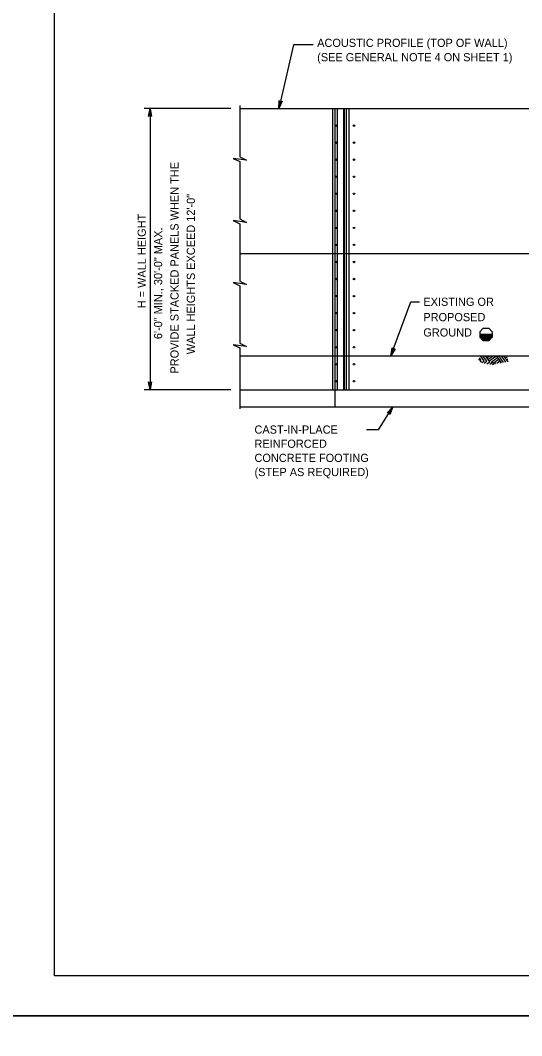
# Model space of a CAD drawing. Extents: x 3385 to 6532, y -616 to 1166.
# Drawn here: x 5470.5 to 5658.6, y 564.2 to 945.5 of the extents above; entities that cross this region are included whole.
import ezdxf

# ---------------------------------------------------------------- set-up
doc = ezdxf.new("R2010")
doc.units = 0
for name, color, linetype in [('1', 7, 'Continuous'), ('2', 7, 'Continuous'), ('PLT-BNDY', 7, 'Continuous')]:
    doc.layers.add(name, color=color, linetype=linetype)

msp = doc.modelspace()

# ---------------------------------------------------------------- linework, layer by layer
at = {"layer": '1'}
for p, q in [((5573, 936.35), (5567.47, 912.36)), ((5580.4, 936.35), (5573, 936.35)), ((5549.4, 912.36), (5516.97, 912.36)), ((5519.16, 912.36), (5519.16, 806.75)), ((5552.78, 913.58), (5552.78, 894.22)), ((5552.78, 912.36), (5684.01, 912.36)), ((5587.59, 912.36), (5587.59, 806.75)), ((5588.65, 806.75), (5588.65, 912.36)), ((5589.53, 806.75), (5589.53, 912.36)), ((5591.91, 806.75), (5591.91, 912.36)), ((5592.15, 806.75), (5592.15, 912.36)), ((5592.77, 912.36), (5592.77, 806.75)), ((5593.85, 806.75), (5593.85, 912.36)), ((5552.78, 892.46), (5552.78, 870.9)), ((5552.78, 869.14), (5552.78, 847.59)), ((5552.78, 857.95), (5771.06, 857.95)), ((5552.78, 845.83), (5552.78, 824.27)), ((5609.52, 819.55), (5617.03, 839.74)), ((5617.03, 839.74), (5620.3, 839.74)), ((5642.89, 827.65), (5647.51, 827.65)), ((5644.16, 829.84), (5642.91, 828.58)), ((5642.91, 828.58), (5642.91, 826.47)), ((5642.92, 827.55), (5647.51, 827.55)), ((5644.16, 829.84), (5646.27, 829.84)), ((5646, 827.65), (5647.51, 827.65)), ((5646.27, 829.84), (5647.52, 828.58)), ((5647.52, 828.58), (5647.52, 826.47)), ((5642.89, 826.55), (5647.51, 826.55)), ((5642.9, 826.95), (5647.51, 826.95)), ((5642.9, 826.85), (5647.51, 826.85)), ((5642.9, 826.75), (5647.51, 826.75)), ((5642.9, 826.65), (5647.51, 826.65)), ((5642.91, 827.45), (5647.51, 827.45)), ((5642.91, 827.35), (5647.51, 827.35)), ((5642.91, 827.25), (5647.51, 827.25)), ((5642.91, 827.15), (5647.51, 827.15)), ((5642.91, 827.05), (5647.51, 827.05)), ((5644.16, 825.21), (5642.91, 826.47)), ((5642.91, 826.45), (5647.47, 826.45)), ((5643.02, 826.35), (5647.37, 826.35)), ((5643.12, 826.25), (5647.28, 826.25)), ((5643.22, 826.15), (5647.18, 826.15)), ((5643.32, 826.05), (5647.08, 826.05)), ((5643.42, 825.95), (5646.99, 825.95)), ((5643.53, 825.85), (5646.89, 825.85)), ((5643.63, 825.75), (5646.8, 825.75)), ((5643.73, 825.65), (5646.7, 825.65)), ((5643.83, 825.55), (5646.6, 825.55)), ((5643.93, 825.45), (5646.51, 825.45)), ((5644.03, 825.35), (5646.41, 825.35)), ((5644.14, 825.25), (5646.32, 825.25)), ((5644.16, 825.21), (5646.27, 825.21)), ((5646.27, 825.21), (5647.52, 826.47)), ((5552.78, 822.51), (5552.78, 799.62)), ((5552.78, 819.55), (5769.29, 819.55)), ((5642.53, 818.1), (5643.01, 818.43)), ((5643.44, 817.81), (5642.74, 818.81)), ((5643.46, 817.13), (5642.91, 817.91)), ((5644.49, 817.63), (5643.15, 819.54)), ((5643.65, 817.04), (5644.49, 817.63)), ((5645.54, 817.45), (5644.07, 819.53)), ((5644.55, 816.75), (5645.54, 817.45)), ((5646.59, 817.26), (5645, 819.53)), ((5645.07, 819.42), (5645.23, 819.53)), ((5645.51, 818.81), (5646.54, 819.53)), ((5645.58, 816.56), (5646.59, 817.26)), ((5645.94, 818.19), (5647.84, 819.53)), ((5646.38, 817.57), (5647.92, 818.66)), ((5646.62, 816.36), (5647.64, 817.08)), ((5647.12, 817.17), (5647.73, 817.6)), ((5648.22, 816.25), (5647.64, 817.08)), ((5647.65, 816.16), (5648.08, 816.46)), ((5647.73, 817.6), (5649.59, 818.91)), ((5647.92, 818.66), (5649.15, 819.52)), ((5648.17, 816.99), (5650.02, 818.29)), ((5648.95, 816.52), (5648.69, 816.9)), ((5651, 816.9), (5649.15, 819.52)), ((5649.22, 816.8), (5650.45, 817.67)), ((5651.84, 817.02), (5650.08, 819.52)), ((5650.58, 816.84), (5650.89, 817.05)), ((5652.67, 817.13), (5651, 819.52)), ((5653.51, 817.25), (5651.92, 819.52)), ((5652.09, 819.28), (5652.42, 819.51)), ((5652.52, 818.66), (5653.17, 819.12)), ((5652.96, 818.05), (5653.35, 818.32)), ((5653.39, 817.43), (5653.53, 817.53)), ((5549.4, 806.75), (5516.97, 806.75)), ((5552.78, 806.75), (5771.3, 806.75)), ((5588.55, 800.35), (5588.55, 806.75)), ((5552.78, 800.35), (5752.12, 800.35)), ((5604.84, 791.67), (5610.23, 800.35)), ((5604.84, 791.67), (5600.37, 791.67))]:
    msp.add_line(p, q, dxfattribs=at)
for points in [[(5567.47, 912.36), (5567.6, 915.39), (5567.7, 915.13), (5567.87, 914.97), (5568.06, 914.89), (5568.26, 914.88), (5568.48, 914.95), (5568.69, 915.14), (5567.47, 912.36), (5568.48, 914.95), (5568.26, 914.88), (5567.47, 912.36), (5568.06, 914.89), (5567.87, 914.97), (5567.47, 912.36), (5567.7, 915.13)], [(5519.16, 912.36), (5519.72, 909.37), (5519.56, 909.6), (5519.36, 909.72), (5519.16, 909.76), (5518.96, 909.72), (5518.76, 909.6), (5518.6, 909.37), (5519.16, 912.36), (5518.76, 909.6), (5518.96, 909.72), (5519.16, 912.36), (5519.16, 909.76), (5519.36, 909.72), (5519.16, 912.36), (5519.56, 909.6)], [(5552.78, 894.22), (5555.37, 892.95), (5550.29, 893.64), (5552.78, 892.46)], [(5552.78, 870.9), (5555.37, 869.63), (5550.29, 870.32), (5552.78, 869.14)], [(5552.78, 847.59), (5555.37, 846.32), (5550.29, 847.01), (5552.78, 845.83)], [(5552.78, 824.27), (5555.37, 823), (5550.29, 823.69), (5552.78, 822.51)], [(5609.52, 819.55), (5610.04, 822.54), (5610.07, 822.41), (5610.11, 822.27), (5610.18, 822.18), (5610.25, 822.09), (5610.34, 822.04), (5610.43, 821.99), (5610.53, 821.97), (5610.63, 821.95), (5610.74, 821.97), (5610.86, 821.99), (5610.97, 822.07), (5611.08, 822.15), (5609.52, 819.55), (5610.97, 822.07), (5610.86, 821.99), (5609.52, 819.55), (5610.74, 821.97), (5610.63, 821.95), (5609.52, 819.55), (5610.53, 821.97), (5610.43, 821.99), (5609.52, 819.55), (5610.34, 822.04), (5610.25, 822.09), (5609.52, 819.55), (5610.18, 822.18), (5610.11, 822.27), (5609.52, 819.55), (5610.07, 822.41)], [(5519.16, 806.75), (5518.6, 809.74), (5518.68, 809.62), (5518.76, 809.51), (5518.86, 809.45), (5518.96, 809.39), (5519.06, 809.37), (5519.16, 809.35), (5519.26, 809.37), (5519.36, 809.39), (5519.46, 809.45), (5519.56, 809.51), (5519.64, 809.62), (5519.72, 809.74), (5519.16, 806.75), (5519.64, 809.62), (5519.56, 809.51), (5519.16, 806.75), (5519.46, 809.45), (5519.36, 809.39), (5519.16, 806.75), (5519.26, 809.37), (5519.16, 809.35), (5519.16, 806.75), (5519.06, 809.37), (5518.96, 809.39), (5519.16, 806.75), (5518.86, 809.45), (5518.76, 809.51), (5519.16, 806.75), (5518.68, 809.62)], [(5610.23, 800.35), (5609.13, 797.52), (5609.12, 797.8), (5609.01, 798.01), (5608.86, 798.15), (5608.67, 798.22), (5608.44, 798.23), (5608.18, 798.11), (5610.23, 800.35), (5608.44, 798.23), (5608.67, 798.22), (5610.23, 800.35), (5608.86, 798.15), (5609.01, 798.01), (5610.23, 800.35), (5609.12, 797.8)]]:
    msp.add_lwpolyline(points, dxfattribs=at)
for centre in [(5589.09, 905.96), (5595.66, 905.96), (5589.09, 899.56), (5595.66, 899.56), (5589.09, 893.16), (5595.66, 893.16), (5589.09, 886.76), (5595.66, 886.76), (5589.09, 880.36), (5595.66, 880.36), (5589.09, 873.96), (5595.66, 873.96), (5589.09, 867.56), (5595.66, 867.56), (5589.09, 861.15), (5595.66, 861.15), (5589.09, 854.75), (5595.66, 854.75), (5589.09, 848.35), (5595.66, 848.35), (5589.09, 841.95), (5595.66, 841.95), (5589.09, 835.55), (5595.66, 835.55), (5589.09, 829.15), (5595.66, 829.15), (5589.09, 822.75), (5595.66, 822.75), (5589.09, 816.35), (5595.66, 816.35), (5589.09, 809.95), (5595.66, 809.95)]:
    msp.add_circle(centre, 0.267, dxfattribs=at)
at = {"layer": '2'}
for p, q in [((5483.34, 586.69), (5483.34, 1150.69)), ((6269.34, 586.69), (5483.34, 586.69))]:
    msp.add_line(p, q, dxfattribs=at)
at = {"layer": 'PLT-BNDY'}
for points in [[(5443.34, 1165.69), (6284.34, 1165.69), (6284.34, 571.69), (5443.34, 571.69)], [(5443.34, 571.69), (6284.34, 571.69), (6284.34, -22.31), (5443.34, -22.31)]]:
    msp.add_lwpolyline(points, close=True, dxfattribs=at)

# ---------------------------------------------------------------- texts
at = {"layer": '1'}
for s, height, p in [('ACOUSTIC PROFILE (TOP OF WALL)', 3.072, (5581.86, 935.51)), ('(SEE GENERAL NOTE 4 ON SHEET 1)', 3.072, (5581.86, 930.13)), ('EXISTING OR ', 3.072, (5621.7, 838.28)), ('PROPOSED', 3.072, (5621.7, 832.52)), ('GROUND', 3.072, (5621.7, 826.76)), ('CAST-IN-PLACE', 3.0721, (5558.33, 790.28)), ('REINFORCED', 3.072, (5558.33, 784.97)), ('CONCRETE FOOTING', 3.0721, (5558.33, 779.65)), ('(STEP AS REQUIRED)', 3.0721, (5558.33, 774.34))]:
    msp.add_text(s, height=height, dxfattribs=at).set_placement(p)
for s, p in [('PROVIDE STACKED PANELS WHEN THE', (5529.84, 812.86)), ('WALL HEIGHTS EXCEED 12\'-0"', (5535.99, 820.1)), ('H = WALL HEIGHT', (5517.55, 837.36)), ('6\'-0" MIN., 30\'-0" MAX.', (5523.7, 825.78))]:
    msp.add_text(s, height=3.072, rotation=90, dxfattribs=at).set_placement(p)

doc.saveas('drawing.dxf')
